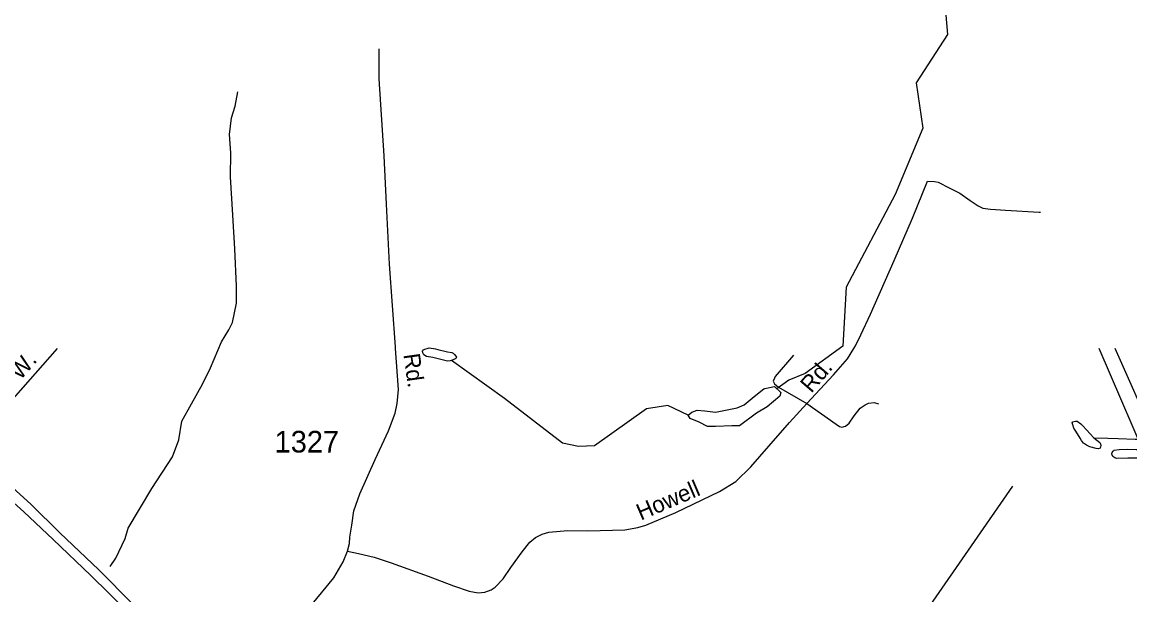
# Model space of a CAD drawing. Extents: x 2260773 to 2342389, y 552869 to 618546.
# Drawn here: x 2281840 to 2288230, y 609332 to 612636 of the extents above; entities that cross this region are included whole.
import ezdxf

# ---------------------------------------------------------------- set-up
doc = ezdxf.new("R2010")
doc.units = 0
for name, color, linetype in [('Exist Boundary Political Urban Extension UEB', 7, 'Continuous'), ('Exist Hydrographic Misc Water Feature', 7, 'Continuous'), ('Exist Road Non-System Type 51', 7, 'Continuous'), ('Exist Road Non-System Type 51 Label', 7, 'Continuous'), ('Exist Road Primary US Divided Attributed', 7, 'Continuous'), ('Exist Road Secondary Type 51 Attributed', 7, 'Continuous'), ('Exist Road Secondary Type 51 Label', 7, 'Continuous'), ('Exist Road Secondary Type 51 Number Label', 7, 'Continuous'), ('Exist Utilities Electrical Transmission Line', 7, 'Continuous')]:
    doc.layers.add(name, color=color, linetype=linetype)

msp = doc.modelspace()

# ---------------------------------------------------------------- linework, layer by layer
at = {"layer": 'Exist Boundary Political Urban Extension UEB'}
msp.add_line((2289380.7, 607963.8), (2288145.2, 610753.3), dxfattribs=at)
at = {"layer": 'Exist Hydrographic Misc Water Feature'}
for points in [[(2288259.9, 613067.1), (2288006.7, 613487.9), (2287933.2, 613492), (2287871.9, 613340.8), (2287349.2, 613103.8), (2287218.5, 613009.8), (2287161.3, 612768.8), (2287177.7, 612564.5), (2286998, 612286.6), (2287036.5, 612025.1), (2286875.5, 611641.1), (2286594.5, 611106.3), (2286574, 610766.9), (2286358.1, 610609.2), (2286262.2, 610571.5), (2286194.3, 610520.7)], [(2282347, 609495.4), (2282379.4, 609543.1), (2282434.4, 609657.3), (2282451.8, 609716.5), (2282587.7, 609946.5), (2282707.5, 610127.9), (2282742.9, 610226), (2282761.4, 610334.3), (2282816.8, 610434.7), (2282879.7, 610547.2), (2282927.3, 610641.8), (2282990, 610791.6), (2283031.7, 610861.3), (2283052.6, 610903.1), (2283077, 611014.7), (2283077, 611112.2), (2283066.6, 611328.3), (2283056.1, 611523.4), (2283042.2, 611743), (2283042.7, 611882), (2283036.2, 611988.1), (2283047, 612084.2), (2283068.1, 612152.3), (2283083.5, 612234.4)], [(2284278.7, 610684.7), (2284208.2, 610700.6), (2284172.9, 610707.5), (2284157.3, 610717.3), (2284151.3, 610728), (2284148.9, 610737.7), (2284154.6, 610745.1), (2284163.4, 610749.5), (2284176.9, 610754.2), (2284188.1, 610757.4), (2284224.9, 610751.3), (2284238.1, 610746.7), (2284293.9, 610734.6), (2284318.6, 610729.4), (2284326.9, 610726.6), (2284334.8, 610719.4), (2284342, 610709.9), (2284345.5, 610702.6), (2284342.1, 610696.5), (2284335, 610692.5), (2284326.2, 610688.5), (2284308.9, 610681.7), (2284293.7, 610681.1), (2284278.7, 610684.7)], [(2285683.1, 610369.3), (2285564.8, 610423.6), (2285441.5, 610404.3), (2285141.2, 610192.4), (2285048.7, 610188.5), (2284956.3, 610207.8), (2284621.6, 610465.2), (2284316.8, 610684.8)], [(2286125.1, 610523.5), (2286179.9, 610533.8), (2286217.6, 610499.5), (2286210.8, 610479), (2286138.8, 610417.3), (2286077.2, 610379.5), (2285977.8, 610307.6), (2285933.2, 610307.6), (2285840.7, 610304.1), (2285792.8, 610304.1), (2285744.8, 610328.1), (2285693.4, 610348.7), (2285683.1, 610369.3), (2285703.7, 610386.4), (2285734.5, 610396.7), (2285779.1, 610393.3), (2285840.7, 610386.4), (2285964.1, 610410.4), (2286005.2, 610427.5), (2286063.4, 610475.5), (2286118.3, 610520.1), (2286125.1, 610523.5)], [(2288023.4, 610237.9), (2288057.7, 610210.4), (2288061.8, 610202.5), (2288063.8, 610194.5), (2288062, 610186.2), (2288058.3, 610178.3), (2288048.2, 610174.2), (2288035.7, 610176), (2288000.1, 610185.8), (2287980, 610195.4), (2287963.6, 610207.6), (2287951.7, 610223.1), (2287943.5, 610236.9), (2287919.1, 610276.7), (2287906.8, 610292.8), (2287901.2, 610312.7), (2287896.9, 610324.7), (2287900.8, 610330.6), (2287908.8, 610332.6), (2287916.8, 610334.7), (2287926.6, 610333.2), (2287946.9, 610319.2), (2287959, 610307.2), (2288023.4, 610237.9)], [(2288023.4, 610237.9), (2288103.6, 610236.7), (2288163.5, 610233.4), (2288261.5, 610230), (2288333.5, 610230.9), (2288397.4, 610227.4), (2288457.3, 610222)], [(2288306.8, 610134.4), (2288282.8, 610120.5), (2288218.4, 610119.7), (2288154.7, 610119.1), (2288144.2, 610123.1), (2288132.3, 610131), (2288126.4, 610142.9), (2288128.4, 610152.7), (2288134.4, 610161.1), (2288140.1, 610167.2), (2288168, 610171.5), (2288218.2, 610171.6), (2288266, 610170.1), (2288283.9, 610170.3), (2288297.8, 610162.5), (2288304.4, 610152.6), (2288308, 610142.7), (2288306.8, 610134.4)]]:
    msp.add_lwpolyline(points, dxfattribs=at)
at = {"layer": 'Exist Road Non-System Type 51'}
for points in [[(2282041.1, 610753.3), (2281759.2, 610432.6), (2281687.5, 610355.9), (2281665.2, 610316.3), (2281645.4, 610207.4), (2281561.2, 610138.5)], [(2286290.2, 610715.1), (2286183.4, 610592.1), (2286179.6, 610582.2), (2286171.6, 610564), (2286179.7, 610550.2), (2286203.9, 610530.3), (2286366.7, 610436.6)], [(2286366.7, 610436.6), (2286535.5, 610316.6), (2286556.2, 610303.3), (2286568, 610298.8), (2286590.2, 610304.8), (2286611, 610322.5), (2286640.6, 610364), (2286674.6, 610408.4), (2286702.7, 610429.2), (2286722, 610438.1), (2286756, 610441), (2286779.7, 610433.6)], [(2285720.9, 607521.8), (2286325.9, 608131.9), (2286896.7, 608718.1), (2286995.2, 608832.7), (2286992, 608852.1), (2286987.1, 608889.3), (2286982.3, 608918.3), (2286962.9, 608968.4), (2286945.2, 609028.1), (2286945.2, 609050.8), (2286948.4, 609066.9), (2286962.9, 609099.2), (2287077.5, 609270.4), (2287555.3, 609958.4)]]:
    msp.add_lwpolyline(points, dxfattribs=at)
at = {"layer": 'Exist Road Primary US Divided Attributed'}
for points in [[(2283149.6, 608800.9), (2282982.6, 608907.7), (2282740.3, 609069.3), (2282478.4, 609278.7), (2282282.6, 609475.9), (2282056.5, 609689.7), (2281891.2, 609853.3), (2281631.4, 610087)], [(2281593.5, 610039.2), (2281849.3, 609811.4), (2282019.4, 609651), (2282236, 609442.8), (2282445.3, 609238.3), (2282699.9, 609033.8), (2282868.8, 608918.7), (2282986.3, 608839.1), (2283116.4, 608756.4)]]:
    msp.add_lwpolyline(points, dxfattribs=at)
at = {"layer": 'Exist Road Secondary Type 51 Attributed'}
for points in [[(2283717.1, 609583.9), (2283729.2, 609628.3), (2283731.1, 609665.2), (2283742.3, 609734.5), (2283753.9, 609817.6), (2283788.3, 609915.3), (2283877.1, 610112.2), (2283954.1, 610278.1), (2283991.1, 610380.3), (2284002.9, 610436.6), (2284011.8, 610516.5), (2283993.7, 610753.3), (2283992.9, 610763.5), (2283958.5, 611240.7), (2283940.8, 611585.8), (2283927.5, 611864.2), (2283899.3, 612308.5), (2283899.3, 612400.4), (2283899.3, 612483.3)], [(2283717.1, 609583.9), (2283780.2, 609571.3), (2283869.8, 609548.4), (2283968.3, 609516.8), (2284182.7, 609439), (2284328.6, 609383.6), (2284418.9, 609354), (2284470.7, 609343.6), (2284509.2, 609348.1), (2284544.7, 609359.9), (2284568.4, 609376.2), (2284614.2, 609425.1), (2284658.6, 609490.2), (2284723.8, 609580.6), (2284768.2, 609635.4), (2284802.2, 609662), (2284839.2, 609681.3), (2284877.7, 609693.1), (2284987.2, 609703.5), (2285104.2, 609700.5), (2285317.3, 609706.4), (2285391.3, 609721.3), (2285438.7, 609734.6), (2285610.4, 609807.2), (2285863.5, 609928.6), (2285956.7, 609986.4), (2286044.1, 610070.8), (2286147.7, 610190.7), (2286266.1, 610327), (2286366.7, 610436.6), (2286520.7, 610601), (2286600.6, 610692.8), (2286638.6, 610753.3), (2286648, 610768.3), (2286679.1, 610832), (2286733.8, 610950.5), (2286870, 611261.5), (2286976.6, 611505.8), (2287062.4, 611719.1), (2287103.9, 611717.6), (2287123.8, 611713.9), (2287192.7, 611679.1), (2287250.4, 611649.5), (2287309.6, 611606.5), (2287355.5, 611576.9), (2287382.1, 611563.6), (2287426.5, 611557.7), (2287513.9, 611551.8), (2287706.3, 611539.9), (2287715, 611539.2)], [(2283149.6, 608800.9), (2283190.5, 608853.4), (2283371.3, 609105.7), (2283637.2, 609430.6), (2283690.8, 609523.1), (2283717.1, 609583.9)]]:
    msp.add_lwpolyline(points, dxfattribs=at)
at = {"layer": 'Exist Utilities Electrical Transmission Line'}
msp.add_line((2289356.4, 607719.2), (2288052.7, 610753.3), dxfattribs=at)

# ---------------------------------------------------------------- texts
at = {"layer": 'Exist Road Non-System Type 51 Label'}
msp.add_text('W.', height=95, rotation=49.25059, dxfattribs=at).set_placement((2281829.3, 610566.1))
at = {"layer": 'Exist Road Secondary Type 51 Label'}
for s, rotation, p in [('Rd.', 278.00446, (2284039.2, 610718.7)), ('Rd.', 49.20604, (2286392.2, 610492)), ('Howell', 23.08218, (2285408.9, 609760))]:
    msp.add_text(s, height=95, rotation=rotation, dxfattribs=at).set_placement(p)
at = {"layer": 'Exist Road Secondary Type 51 Number Label'}
msp.add_text('1327', height=125, dxfattribs=at).set_placement((2283296.3, 610153.2))

doc.saveas('drawing.dxf')
